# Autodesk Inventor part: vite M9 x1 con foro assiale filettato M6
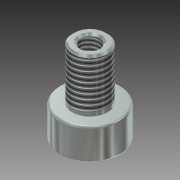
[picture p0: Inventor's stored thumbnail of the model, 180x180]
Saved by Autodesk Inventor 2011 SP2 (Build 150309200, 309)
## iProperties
Created: 2018-03
Part Number: vite M9 x1 con foro assiale filettato M6
Document SubType Name: Modeling
Designer: 18619647
Density: 1 g/cm^3
Author: 18619647
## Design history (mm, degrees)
sketch "Schizzo1"
  geometry: C1 r 7.75 at (0, 0); 1 further point
  constraints: 1 centre point, 1 coincident
  dimensions: "d0" = 15.5 diameter of C1
extrude "Estrusione1" new body sketch "Schizzo1" distance "d1" = 8; taper "d2" = 0 deg
sketch "Schizzo2"
  geometry: C1 r 7.75 at (0, 0) reference; C2 r 4.5 at (0, 0)
  constraints: 1 centre point, 1 coincident
  dimensions: "d3" = 9 diameter of C2
extrude "Estrusione2" join sketch "Schizzo2" distance "d4" = 13.5; taper "d5" = 0 deg
feature "Filettatura1" dims "d6" = 12.5, "d7" = 1
chamfer "Smusso1" distance "d8" = 0.5; stored, may be unused: second distance "d9" = 2, angle "d10" = 45 deg
sketch "Schizzo3"
  geometry: L1 (-5, 2.887)-(-3.66, 3.66); L2 (-1.34, 5)-(0, 5.774); L3 (-5.774, 0)-(-5, 1.34); L4 (-3.66, 3.66)-(-2.887, 5); L5 (-5, -2.887)-(-5, -1.34); L6 (-5, 1.34)-(-5, 2.887); L7 (-2.887, -5)-(-3.66, -3.66); L8 (-5, -1.34)-(-5.774, 0); L9 (0, -5.774)-(-1.34, -5); L10 (-3.66, -3.66)-(-5, -2.887); L11 (2.887, -5)-(1.34, -5); L12 (-1.34, -5)-(-2.887, -5); L13 (5, -2.887)-(3.66, -3.66); L14 (1.34, -5)-(0, -5.774); L15 (5.774, 0)-(5, -1.34); L16 (3.66, -3.66)-(2.887, -5); L17 (5, 2.887)-(5, 1.34); L18 (5, -1.34)-(5, -2.887); L19 (2.887, 5)-(3.66, 3.66); L20 (5, 1.34)-(5.774, 0); L21 (0, 5.774)-(1.34, 5); L22 (3.66, 3.66)-(5, 2.887); L23 (-2.887, 5)-(-1.34, 5); L24 (1.34, 5)-(2.887, 5); C1 r 7.75 at (0, 0) reference; 2 further points
  constraints: 48 end point, 2 coincident, 8 other
extrude "Estrusione3" cut sketch "Schizzo3" distance "d13" = 5; taper "d14" = 0 deg
hole "Hole1" diameter "d17" = 4.917; stored, may be unused: countersink angle "d21" = 90 deg, drill point angle "d23" = 118 deg; dims "d15" = 10, "d16" = 10, "d18" = 6, "d19" = 4, "d20" = 2, "d22" = 8
chamfer "Smusso2" distance "d24" = 0.5; stored, may be unused: second distance "d25" = 2, angle "d26" = 45 deg
fillet "Raccordo1" dims "d27" = 0.5
fillet "Raccordo2" dims "d28" = 0.1
sketch "Schizzo4"
  geometry: L1 (2.458, 21)-(2.958, 21.5) reference; L2 (2.958, 21.5)-(4, 21.5) reference; L3 (4, 21.5)-(4.5, 21) reference; L4 (4.5, 21)-(4.5, 8.1) reference; L5 (4.6, 8)-(7.25, 8) reference; L6 (7.75, 7.5)-(7.75, 0.5) reference; L7 (7.25, 0)-(5.774, 0) reference; L8 (5.774, 0)-(5.774, 5) reference; L9 (5.774, 5)-(2.958, 5) reference; L10 (2.958, 5)-(2.458, 5.5) reference; L11 (2.458, 5.5)-(2.458, 21) reference; L12 (-2.958, 21.5)-(-2.458, 21) reference; L13 (-2.458, 21)-(-2.458, 5.5) reference; L14 (-2.458, 5.5)-(-2.958, 5) reference; L15 (-2.958, 5)-(-5.774, 5) reference; L16 (-5.774, 5)-(-5.774, 0) reference; L17 (-5.774, 0)-(-7.25, 0) reference; L18 (-7.75, 0.5)-(-7.75, 7.5) reference; L19 (-7.25, 8)-(-4.6, 8) reference; L20 (-4.5, 8.1)-(-4.5, 21) reference; L21 (-4.5, 21)-(-4, 21.5) reference; L22 (-4, 21.5)-(-2.958, 21.5) reference; L23 (5.774, 0)-(5.924, 0); L24 (5.924, 0)-(4.826, 1.097); L25 (4.826, 1.097)-(4.826, 0); L26 (4.826, 0)-(5.774, 0); L27 (0, -4.424)-(0, 25.821) reference; A1 r 0.1 centre (4.6, 8.1) between (4.5, 8.1) and (4.6, 8) reference; A2 r 0.5 centre (7.25, 7.5) between (7.75, 7.5) and (7.25, 8) reference; A3 r 0.5 centre (7.25, 0.5) between (7.25, 0) and (7.75, 0.5) reference; A4 r 0.5 centre (-7.25, 0.5) between (-7.75, 0.5) and (-7.25, 0) reference; A5 r 0.5 centre (-7.25, 7.5) between (-7.25, 8) and (-7.75, 7.5) reference; A6 r 0.1 centre (-4.6, 8.1) between (-4.6, 8) and (-4.5, 8.1) reference; 1 further point
  constraints: 8 end point, 1 parallel, 1 perpendicular, 1 point on line
  dimensions: "d29" = 0.15 distance of L7.end L23.end; "d30" = 45 deg angle of L24 L23
revolve "Rivoluzione1" sketch "Schizzo4" stored, may be unused: angle "d31" = 90 deg
node "Solido1"
node "Proietta spigoli di taglio1"
